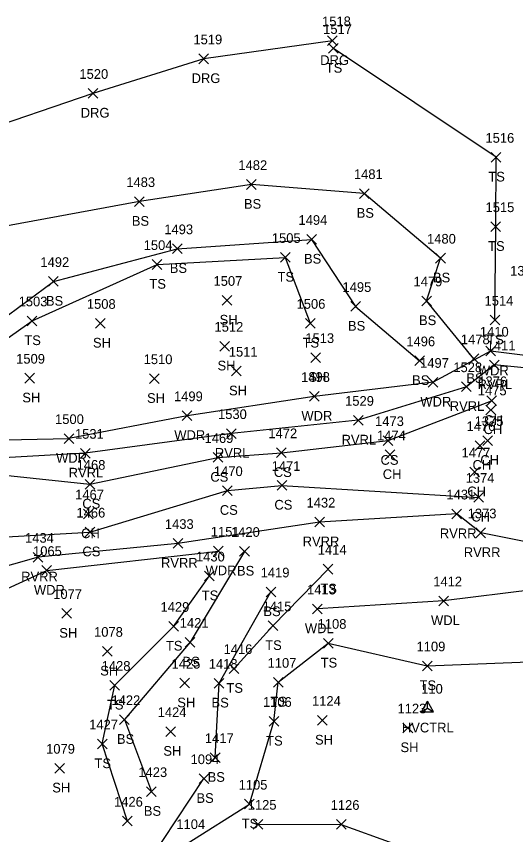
# Model space of a CAD drawing. Extents: x 1621633 to 1624015, y 417863 to 420979.
# Drawn here: x 1622010.4 to 1622113.6, y 418184 to 418353 of the extents above; entities that cross this region are included whole.
import ezdxf

# ---------------------------------------------------------------- set-up
doc = ezdxf.new("R2010")
doc.units = 0
for name, color, linetype in [('C_A', 7, 'Continuous'), ('C_I', 7, 'Continuous'), ('CPSM', 7, 'Continuous'), ('L_A', 7, 'Continuous'), ('L_I', 7, 'Continuous'), ('L_TIC', 7, 'Continuous'), ('LAWA', 7, 'Continuous'), ('LAWE', 7, 'Continuous'), ('LELB', 7, 'Continuous'), ('R_A', 7, 'Continuous'), ('R_I', 7, 'Continuous'), ('R_TIC', 7, 'Continuous'), ('RDG', 7, 'Continuous')]:
    doc.layers.add(name, color=color, linetype=linetype)

msp = doc.modelspace()

# ---------------------------------------------------------------- linework, layer by layer
at = {"layer": 'CPSM'}
for p, q in [((1622094.16, 418209.42), (1622095.41, 418211.59)), ((1622094.16, 418209.42), (1622095.41, 418210.14)), ((1622096.66, 418209.42), (1622095.41, 418211.59)), ((1622095.41, 418210.14), (1622095.41, 418211.59)), ((1622095.41, 418210.14), (1622095.41, 418210.14)), ((1622095.41, 418210.14), (1622096.66, 418209.42)), ((1622094.16, 418209.42), (1622096.66, 418209.42))]:
    msp.add_line(p, q, dxfattribs=at)
at = {"layer": 'L_TIC'}
for points in [[(1622074.96, 418345.37), (1622076.96, 418347.37)], [(1622076.96, 418345.37), (1622074.96, 418347.37)], [(1622108.55, 418322.9), (1622110.55, 418324.9)], [(1622110.55, 418322.9), (1622108.55, 418324.9)], [(1622058.02, 418317.28), (1622060.02, 418319.28)], [(1622060.02, 418317.28), (1622058.02, 418319.28)], [(1622081.32, 418315.41), (1622083.32, 418317.41)], [(1622083.32, 418315.41), (1622081.32, 418317.41)], [(1622034.86, 418313.76), (1622036.86, 418315.76)], [(1622036.86, 418313.76), (1622034.86, 418315.76)], [(1622108.51, 418308.58), (1622110.51, 418310.58)], [(1622110.51, 418308.58), (1622108.51, 418310.58)], [(1622070.43, 418305.95), (1622072.43, 418307.95)], [(1622072.43, 418305.95), (1622070.43, 418307.95)], [(1622042.7, 418304.02), (1622044.7, 418306.02)], [(1622044.7, 418304.02), (1622042.7, 418306.02)], [(1622065, 418302.22), (1622067, 418304.22)], [(1622067, 418302.22), (1622065, 418304.22)], [(1622097.08, 418302.07), (1622099.08, 418304.07)], [(1622099.08, 418302.07), (1622097.08, 418304.07)], [(1622038.52, 418300.76), (1622040.52, 418302.76)], [(1622040.52, 418300.76), (1622038.52, 418302.76)], [(1622017.11, 418297.26), (1622019.11, 418299.26)], [(1622019.11, 418297.26), (1622017.11, 418299.26)], [(1622052.95, 418293.36), (1622054.95, 418295.36)], [(1622054.95, 418293.36), (1622052.95, 418295.36)], [(1622094.2, 418293.25), (1622096.2, 418295.25)], [(1622096.2, 418293.25), (1622094.2, 418295.25)], [(1622079.52, 418292.1), (1622081.52, 418294.1)], [(1622081.52, 418292.1), (1622079.52, 418294.1)], [(1622012.68, 418289.12), (1622014.68, 418291.12)], [(1622014.68, 418289.12), (1622012.68, 418291.12)], [(1622108.31, 418289.28), (1622110.31, 418291.28)], [(1622110.31, 418289.28), (1622108.31, 418291.28)], [(1622026.78, 418288.61), (1622028.78, 418290.61)], [(1622028.78, 418288.61), (1622026.78, 418290.61)], [(1622070.17, 418288.62), (1622072.17, 418290.62)], [(1622072.17, 418288.62), (1622070.17, 418290.62)], [(1622052.51, 418283.89), (1622054.51, 418285.89)], [(1622054.51, 418283.89), (1622052.51, 418285.89)], [(1622107.44, 418282.87), (1622109.44, 418284.87)], [(1622109.44, 418282.87), (1622107.44, 418284.87)], [(1622071.27, 418281.55), (1622073.27, 418283.55)], [(1622073.27, 418281.55), (1622071.27, 418283.55)], [(1622092.77, 418280.88), (1622094.77, 418282.88)], [(1622094.77, 418280.88), (1622092.77, 418282.88)], [(1622103.98, 418281.3), (1622105.98, 418283.3)], [(1622105.98, 418281.3), (1622103.98, 418283.3)], [(1622108.18, 418280.03), (1622110.18, 418282.03)], [(1622110.18, 418280.03), (1622108.18, 418282.03)], [(1622012.18, 418277.29), (1622014.18, 418279.29)], [(1622014.18, 418277.29), (1622012.18, 418279.29)], [(1622054.9, 418278.74), (1622056.9, 418280.74)], [(1622056.9, 418278.74), (1622054.9, 418280.74)], [(1622037.95, 418277.19), (1622039.95, 418279.19)], [(1622039.95, 418277.19), (1622037.95, 418279.19)], [(1622095.55, 418276.43), (1622097.55, 418278.43)], [(1622097.55, 418276.43), (1622095.55, 418278.43)], [(1622102.42, 418275.53), (1622104.42, 418277.53)], [(1622104.42, 418275.53), (1622102.42, 418277.53)], [(1622070.98, 418273.52), (1622072.98, 418275.52)], [(1622072.98, 418273.52), (1622070.98, 418275.52)], [(1622107.64, 418272.64), (1622109.64, 418274.64)], [(1622109.64, 418272.64), (1622107.64, 418274.64)], [(1622107.48, 418270.74), (1622109.48, 418272.74)], [(1622109.48, 418270.74), (1622107.48, 418272.74)], [(1622044.71, 418269.54), (1622046.71, 418271.54)], [(1622046.71, 418269.54), (1622044.71, 418271.54)], [(1622080.07, 418268.59), (1622082.07, 418270.59)], [(1622082.07, 418268.59), (1622080.07, 418270.59)], [(1622053.89, 418265.85), (1622055.89, 418267.85)], [(1622055.89, 418265.85), (1622053.89, 418267.85)], [(1622020.3, 418264.82), (1622022.3, 418266.82)], [(1622022.3, 418264.82), (1622020.3, 418266.82)], [(1622086.25, 418264.4), (1622088.25, 418266.4)], [(1622088.25, 418264.4), (1622086.25, 418266.4)], [(1622106.83, 418264.41), (1622108.83, 418266.41)], [(1622108.83, 418264.41), (1622106.83, 418266.41)], [(1622105.21, 418263.38), (1622107.21, 418265.38)], [(1622107.21, 418263.38), (1622105.21, 418265.38)], [(1622023.68, 418261.78), (1622025.68, 418263.78)], [(1622025.68, 418261.78), (1622023.68, 418263.78)], [(1622051.08, 418260.91), (1622053.08, 418262.91)], [(1622053.08, 418260.91), (1622051.08, 418262.91)], [(1622064.2, 418261.89), (1622066.2, 418263.89)], [(1622066.2, 418261.89), (1622064.2, 418263.89)], [(1622086.66, 418261.47), (1622088.66, 418263.47)], [(1622088.66, 418261.47), (1622086.66, 418263.47)], [(1622104.12, 418257.91), (1622106.12, 418259.91)], [(1622106.12, 418257.91), (1622104.12, 418259.91)], [(1622024.63, 418255.38), (1622026.63, 418257.38)], [(1622026.63, 418255.38), (1622024.63, 418257.38)], [(1622053.04, 418254.07), (1622055.04, 418256.07)], [(1622055.04, 418254.07), (1622053.04, 418256.07)], [(1622064.32, 418255.15), (1622066.32, 418257.15)], [(1622066.32, 418255.15), (1622064.32, 418257.15)], [(1622104.96, 418252.68), (1622106.96, 418254.68)], [(1622106.96, 418252.68), (1622104.96, 418254.68)], [(1622024.33, 418249.25), (1622026.33, 418251.25)], [(1622026.33, 418249.25), (1622024.33, 418251.25)], [(1622100.43, 418249.25), (1622102.43, 418251.25)], [(1622102.43, 418249.25), (1622100.43, 418251.25)], [(1622072.09, 418247.58), (1622074.09, 418249.58)], [(1622074.09, 418247.58), (1622072.09, 418249.58)], [(1622024.65, 418245.51), (1622026.65, 418247.51)], [(1622026.65, 418245.51), (1622024.65, 418247.51)], [(1622105.38, 418245.35), (1622107.38, 418247.35)], [(1622107.38, 418245.35), (1622105.38, 418247.35)], [(1622042.82, 418243.16), (1622044.82, 418245.16)], [(1622044.82, 418243.16), (1622042.82, 418245.16)], [(1622013.93, 418240.31), (1622015.93, 418242.31)], [(1622015.93, 418240.31), (1622013.93, 418242.31)], [(1622051.18, 418241.59), (1622053.18, 418243.59)], [(1622053.18, 418241.59), (1622051.18, 418243.59)], [(1622056.58, 418241.52), (1622058.58, 418243.52)], [(1622058.58, 418241.52), (1622056.58, 418243.52)], [(1622015.71, 418237.58), (1622017.71, 418239.58)], [(1622017.71, 418237.58), (1622015.71, 418239.58)], [(1622073.85, 418237.85), (1622075.85, 418239.85)], [(1622075.85, 418237.85), (1622073.85, 418239.85)], [(1622049.34, 418236.44), (1622051.34, 418238.44)], [(1622051.34, 418236.44), (1622049.34, 418238.44)], [(1622062.05, 418233.15), (1622064.05, 418235.15)], [(1622064.05, 418233.15), (1622062.05, 418235.15)], [(1622097.7, 418231.3), (1622099.7, 418233.3)], [(1622099.7, 418231.3), (1622097.7, 418233.3)], [(1622019.83, 418228.7), (1622021.83, 418230.7)], [(1622021.83, 418228.7), (1622019.83, 418230.7)], [(1622071.64, 418229.63), (1622073.64, 418231.63)], [(1622073.64, 418229.63), (1622071.64, 418231.63)], [(1622041.93, 418226.04), (1622043.93, 418228.04)], [(1622043.93, 418226.04), (1622041.93, 418228.04)], [(1622062.45, 418226.16), (1622064.45, 418228.16)], [(1622064.45, 418226.16), (1622062.45, 418228.16)], [(1622045.33, 418222.76), (1622047.33, 418224.76)], [(1622047.33, 418222.76), (1622045.33, 418224.76)], [(1622073.9, 418222.54), (1622075.9, 418224.54)], [(1622075.9, 418222.54), (1622073.9, 418224.54)], [(1622028.27, 418220.89), (1622030.27, 418222.89)], [(1622030.27, 418220.89), (1622028.27, 418222.89)], [(1622054.44, 418217.32), (1622056.44, 418219.32)], [(1622056.44, 418217.32), (1622054.44, 418219.32)], [(1622094.34, 418217.88), (1622096.34, 418219.88)], [(1622096.34, 418217.88), (1622094.34, 418219.88)], [(1622029.76, 418213.87), (1622031.76, 418215.87)], [(1622031.76, 418213.87), (1622029.76, 418215.87)], [(1622044.2, 418214.32), (1622046.2, 418216.32)], [(1622046.2, 418214.32), (1622044.2, 418216.32)], [(1622051.33, 418214.29), (1622053.33, 418216.29)], [(1622053.33, 418214.29), (1622051.33, 418216.29)], [(1622063.55, 418214.49), (1622065.55, 418216.49)], [(1622065.55, 418214.49), (1622063.55, 418216.49)], [(1622031.78, 418206.78), (1622033.78, 418208.78)], [(1622033.78, 418206.78), (1622031.78, 418208.78)], [(1622062.65, 418206.42), (1622064.65, 418208.42)], [(1622064.65, 418206.42), (1622062.65, 418208.42)], [(1622072.66, 418206.63), (1622074.66, 418208.63)], [(1622074.66, 418206.63), (1622072.66, 418208.63)], [(1622090.33, 418205.07), (1622092.33, 418207.07)], [(1622092.33, 418205.07), (1622090.33, 418207.07)], [(1622041.33, 418204.32), (1622043.33, 418206.32)], [(1622043.33, 418204.32), (1622041.33, 418206.32)], [(1622027.18, 418201.76), (1622029.18, 418203.76)], [(1622029.18, 418201.76), (1622027.18, 418203.76)], [(1622050.52, 418198.94), (1622052.52, 418200.94)], [(1622052.52, 418198.94), (1622050.52, 418200.94)], [(1622018.37, 418196.74), (1622020.37, 418198.74)], [(1622020.37, 418196.74), (1622018.37, 418198.74)], [(1622048.21, 418194.59), (1622050.21, 418196.59)], [(1622050.21, 418194.59), (1622048.21, 418196.59)], [(1622037.34, 418191.92), (1622039.34, 418193.92)], [(1622039.34, 418191.92), (1622037.34, 418193.92)], [(1622057.58, 418189.33), (1622059.58, 418191.33)], [(1622059.58, 418189.33), (1622057.58, 418191.33)], [(1622032.38, 418185.82), (1622034.38, 418187.82)], [(1622034.38, 418185.82), (1622032.38, 418187.82)], [(1622059.38, 418185.18), (1622061.38, 418187.18)], [(1622061.38, 418185.18), (1622059.38, 418187.18)], [(1622076.57, 418185.15), (1622078.57, 418187.15)], [(1622078.57, 418185.15), (1622076.57, 418187.15)]]:
    msp.add_lwpolyline(points, dxfattribs=at)
at = {"layer": 'LAWA'}
for points in [[(1622334.14, 418235.62), (1622304.57, 418226.13), (1622279.17, 418224.78), (1622252.77, 418236.61), (1622231.24, 418254.76), (1622207.28, 418260.97), (1622182.84, 418269.19), (1622160.31, 418273.27), (1622129.81, 418281.16), (1622108.44, 418283.87), (1622096.55, 418277.43), (1622071.98, 418274.52), (1622045.71, 418270.54), (1622021.3, 418265.82)], [(1622001.65, 418265.43), (1622021.3, 418265.82)], [(1622320.21, 418157.08), (1622282.22, 418156.15), (1622251.71, 418155.08), (1622223.6, 418155.09), (1622209.11, 418155.31), (1622180.88, 418152.89), (1622152.12, 418150.87), (1622117.37, 418144.74), (1622094.14, 418141.69), (1622062.96, 418134.28), (1622030.01, 418125.89), (1622002.09, 418113.22), (1622001.94, 418118.19), (1622004.41, 418142.61), (1621992.55, 418166.21), (1621982.92, 418190.96), (1621974.22, 418213.57), (1621987.21, 418225.09), (1622016.71, 418238.58), (1622052.18, 418242.59)], [(1622294.12, 418161.35), (1622295.35, 418165.31), (1622279.05, 418165.1), (1622262.62, 418162.03), (1622241.27, 418162.89), (1622220.84, 418170.43), (1622210.97, 418182.32), (1622187.59, 418203.03), (1622170.53, 418217.1), (1622143.74, 418224.16), (1622117.62, 418234.62), (1622098.7, 418232.3), (1622072.64, 418230.63)]]:
    msp.add_lwpolyline(points, dxfattribs=at)
at = {"layer": 'LAWE'}
for points in [[(1622333.17, 418232.98), (1622304.92, 418224.43), (1622278.58, 418222.6), (1622250.59, 418234.06), (1622231.09, 418250.9), (1622207.09, 418257.63), (1622185.14, 418265.61), (1622157.85, 418271.29), (1622128.42, 418279.11), (1622109.18, 418281.03), (1622103.42, 418276.53), (1622081.07, 418269.59), (1622054.89, 418266.85), (1622024.68, 418262.78), (1621999.35, 418261.34), (1621980.1, 418259.35), (1621959.54, 418247.53), (1621949.11, 418230.91), (1621945.67, 418206.62), (1621950.84, 418182.3), (1621958.69, 418157.04), (1621962.92, 418133.77), (1621970.23, 418110.89)], [(1622323.31, 418180.93), (1622300.82, 418170.32), (1622276.31, 418168.44), (1622241.72, 418167.29), (1622221.82, 418173.51), (1622205.88, 418194.82), (1622185.97, 418220.63), (1622162.23, 418235.42), (1622129.82, 418241.7), (1622106.38, 418246.35), (1622101.43, 418250.25), (1622073.09, 418248.58), (1622043.82, 418244.16), (1622014.93, 418241.31), (1621989.87, 418234.25), (1621972.68, 418220.99), (1621964.49, 418204.33), (1621969.88, 418176.14), (1621978.91, 418154.62), (1621984.37, 418139.62), (1621989.94, 418122.86), (1621991.15, 418115.14)]]:
    msp.add_lwpolyline(points, dxfattribs=at)
at = {"layer": 'LELB'}
for points in [[(1622109.31, 418290.28), (1622109.51, 418309.58), (1622109.55, 418323.9), (1622075.96, 418346.37)], [(1622104.98, 418282.3), (1622095.2, 418294.25), (1622098.08, 418303.07), (1622082.32, 418316.41), (1622059.02, 418318.28), (1622035.86, 418314.76), (1622004.08, 418308.92), (1621989.1, 418291.93), (1621969.69, 418273.7), (1621958.77, 418259.65)], [(1621997.84, 418270.12), (1621990.09, 418277.31), (1621999.43, 418284.47), (1622018.11, 418298.26), (1622043.7, 418305.02), (1622071.43, 418306.95), (1622080.52, 418293.1), (1622093.77, 418281.88)], [(1621994.58, 418276.65), (1622013.68, 418290.12), (1622039.52, 418301.76), (1622066, 418303.22), (1622071.17, 418289.62)], [(1622087.25, 418265.4), (1622108.64, 418273.64)], [(1621966.69, 418246.42), (1621982.62, 418255.18), (1622002.13, 418258.88), (1622025.63, 418256.38), (1622052.08, 418261.91), (1622065.2, 418262.89), (1622087.25, 418265.4)], [(1621986.07, 418114.57), (1621980.01, 418135.51), (1621971.8, 418158.97), (1621964.78, 418178.35), (1621962.01, 418198.43), (1621960.3, 418210.78), (1621971.3, 418225.2), (1621983.84, 418236.14), (1622007.18, 418245.45), (1622025.65, 418246.51), (1622054.04, 418255.07), (1622065.32, 418256.15)], [(1622065.32, 418256.15), (1622105.96, 418253.68)], [(1622057.58, 418242.52), (1622046.33, 418223.76), (1622032.78, 418207.78), (1622038.34, 418192.92)], [(1622074.85, 418238.85), (1622063.45, 418227.16), (1622055.44, 418218.32)], [(1622033.38, 418186.82), (1622028.18, 418202.76), (1622030.76, 418214.87), (1622042.93, 418227.04), (1622050.34, 418237.44)], [(1622051.52, 418199.94), (1622052.33, 418215.29), (1622063.05, 418234.15)], [(1622012.96, 418144.68), (1622025.55, 418152.7), (1622030.18, 418148.41), (1622040.54, 418132.85), (1622043.38, 418133.51), (1622037.79, 418144.79), (1622034.62, 418151.12), (1622038.47, 418156.73), (1622040.15, 418173.27), (1622045.7, 418182.18), (1622058.58, 418190.33), (1622063.65, 418207.42), (1622064.55, 418215.49), (1622074.9, 418223.54), (1622095.34, 418218.88), (1622118.02, 418219.75), (1622146.4, 418210.35), (1622169.6, 418199.38), (1622194.43, 418184.07), (1622206.1, 418163.37)], [(1622008.25, 418147.12), (1622025.93, 418155.66), (1622030.02, 418153.88), (1622035.92, 418141.6), (1622039.51, 418135.23), (1622041.64, 418135.29), (1622035.33, 418145.89), (1622033.36, 418153.75), (1622037.76, 418161.1), (1622037.88, 418178.56), (1622049.21, 418195.59)], [(1622060.38, 418186.18), (1622077.57, 418186.15), (1622098.9, 418178.4), (1622113.36, 418166.93), (1622113.39, 418154.92)]]:
    msp.add_lwpolyline(points, dxfattribs=at)
at = {"layer": 'R_TIC'}
for points in [[(1622074.73, 418346.97), (1622076.73, 418348.97)], [(1622076.73, 418346.97), (1622074.73, 418348.97)], [(1622048.16, 418343.23), (1622050.16, 418345.23)], [(1622050.16, 418343.23), (1622048.16, 418345.23)], [(1622025.25, 418336.1), (1622027.25, 418338.1)], [(1622027.25, 418336.1), (1622025.25, 418338.1)]]:
    msp.add_lwpolyline(points, dxfattribs=at)
at = {"layer": 'RDG'}
msp.add_lwpolyline([(1622075.73, 418347.97), (1622049.16, 418344.23), (1622026.25, 418337.1), (1622001.6, 418328.7), (1621987.27, 418324.78), (1621966.53, 418312.68)], dxfattribs=at)

# ---------------------------------------------------------------- texts
at = {"layer": 'C_A'}
msp.add_text('HVCTRL', height=2, dxfattribs=at).set_placement((1622090.1, 418205.14))
at = {"layer": 'C_I'}
msp.add_text('110', height=2, dxfattribs=at).set_placement((1622094.09, 418213.14))
at = {"layer": 'L_A'}
for s, p in [('TS', (1622074.37, 418341.37)), ('TS', (1622107.96, 418318.9)), ('BS', (1622057.46, 418313.28)), ('BS', (1622080.76, 418311.41)), ('BS', (1622034.3, 418309.76)), ('TS', (1622107.92, 418304.58)), ('BS', (1622069.87, 418301.95)), ('BS', (1622042.14, 418300.02)), ('TS', (1622064.41, 418298.22)), ('BS', (1622096.52, 418298.07)), ('TS', (1622037.93, 418296.76)), ('BS', (1622016.55, 418293.26)), ('SH', (1622052.44, 418289.36)), ('BS', (1622093.64, 418289.25)), ('BS', (1622078.96, 418288.1)), ('TS', (1622012.09, 418285.12)), ('SH', (1622026.27, 418284.61)), ('TS', (1622069.58, 418284.62)), ('TS', (1622107.72, 418285.28)), ('SH', (1622052, 418279.89)), ('SH', (1622070.76, 418277.55)), ('BS', (1622103.42, 418277.3)), ('WDR', (1622105.8, 418278.87)), ('BS', (1622092.21, 418276.88)), ('RVRL', (1622105.74, 418276.03)), ('SH', (1622054.39, 418274.74)), ('SH', (1622011.67, 418273.29)), ('SH', (1622037.44, 418273.19)), ('WDR', (1622093.92, 418272.43)), ('RVRL', (1622099.99, 418271.53)), ('WDR', (1622069.34, 418269.52)), ('CH', (1622107.12, 418268.64)), ('WDR', (1622043.07, 418265.54)), ('CH', (1622106.97, 418266.74)), ('RVRL', (1622077.64, 418264.59)), ('WDR', (1622018.66, 418260.82)), ('RVRL', (1622051.46, 418261.85)), ('CS', (1622085.69, 418260.4)), ('CH', (1622106.32, 418260.41)), ('CH', (1622104.7, 418259.38)), ('RVRL', (1622021.25, 418257.78)), ('CS', (1622050.52, 418256.91)), ('CS', (1622063.64, 418257.89)), ('CH', (1622086.15, 418257.47)), ('CH', (1622103.61, 418253.91)), ('CS', (1622024.07, 418251.38)), ('CS', (1622063.76, 418251.15)), ('CS', (1622052.48, 418250.07)), ('CH', (1622104.45, 418248.68)), ('CH', (1622023.82, 418245.25)), ('RVRR', (1622097.94, 418245.25)), ('RVRR', (1622069.6, 418243.58)), ('CS', (1622024.09, 418241.51)), ('RVRR', (1622102.89, 418241.35)), ('RVRR', (1622040.33, 418239.16)), ('WDR', (1622049.54, 418237.59)), ('BS', (1622056.02, 418237.52)), ('RVRR', (1622011.44, 418236.31)), ('WDR', (1622014.07, 418233.58)), ('TS', (1622073.26, 418233.85)), ('TS', (1622048.75, 418232.44)), ('BS', (1622061.49, 418229.15)), ('WDL', (1622096.12, 418227.3)), ('WDL', (1622070.06, 418225.63)), ('SH', (1622019.31, 418224.7)), ('TS', (1622041.34, 418222.04)), ('TS', (1622061.86, 418222.16)), ('BS', (1622044.77, 418218.76)), ('TS', (1622073.31, 418218.54)), ('SH', (1622027.76, 418216.89)), ('TS', (1622053.85, 418213.32)), ('TS', (1622093.75, 418213.88)), ('TS', (1622029.17, 418209.87)), ('SH', (1622043.69, 418210.32)), ('BS', (1622050.77, 418210.29)), ('TS', (1622062.96, 418210.49)), ('BS', (1622031.22, 418202.78)), ('TS', (1622062.06, 418202.42)), ('SH', (1622072.15, 418202.63)), ('SH', (1622040.82, 418200.32)), ('SH', (1622089.81, 418201.07)), ('TS', (1622026.59, 418197.76)), ('BS', (1622049.96, 418194.94)), ('SH', (1622017.86, 418192.74)), ('BS', (1622047.65, 418190.59)), ('BS', (1622036.78, 418187.92)), ('TS', (1622056.99, 418185.33))]:
    msp.add_text(s, height=2, dxfattribs=at).set_placement(p)
at = {"layer": 'L_I'}
for s, p in [('1517', (1622073.83, 418349.37)), ('1516', (1622107.37, 418326.9)), ('1482', (1622056.32, 418321.28)), ('1483', (1622033.16, 418317.76)), ('1481', (1622080.19, 418319.41)), ('1515', (1622107.38, 418312.58)), ('1494', (1622068.74, 418309.95)), ('1493', (1622041.01, 418308.02)), ('1505', (1622063.23, 418306.22)), ('1480', (1622095.3, 418306.07)), ('1504', (1622036.75, 418304.76)), ('1492', (1622015.41, 418301.26)), ('1377', (1622112.47, 418299.46)), ('1507', (1622051.18, 418297.36)), ('1495', (1622077.83, 418296.1)), ('1479', (1622092.5, 418297.25)), ('1503', (1622010.91, 418293.12)), ('1508', (1622025.01, 418292.61)), ('1506', (1622068.34, 418292.62)), ('1514', (1622107.18, 418293.28)), ('1512', (1622051.38, 418287.89)), ('1410', (1622106.22, 418286.87)), ('1513', (1622070.15, 418285.55)), ('1496', (1622091.02, 418284.88)), ('1478', (1622102.29, 418285.3)), ('1411', (1622107.62, 418284.03)), ('1511', (1622054.34, 418282.74)), ('1509', (1622010.4, 418281.29)), ('1510', (1622036.74, 418281.19)), ('1497', (1622093.86, 418280.43)), ('1528', (1622100.73, 418279.53)), ('1498', (1622069.28, 418277.52)), ('1376', (1622105.89, 418276.64)), ('1475', (1622105.79, 418274.74)), ('1499', (1622043.01, 418273.54)), ('1529', (1622078.37, 418272.59)), ('1500', (1622018.44, 418268.82)), ('1530', (1622052.11, 418269.85)), ('1473', (1622084.56, 418268.4)), ('1476', (1622103.46, 418267.38)), ('1375', (1622105.14, 418268.41)), ('1531', (1622022.55, 418265.78)), ('1472', (1622062.51, 418265.89)), ('1474', (1622084.97, 418265.47)), ('1469', (1622049.33, 418264.91)), ('1477', (1622102.43, 418261.91)), ('1468', (1622022.89, 418259.38)), ('1471', (1622063.19, 418259.15)), ('1470', (1622051.26, 418258.07)), ('1374', (1622103.27, 418256.68)), ('1467', (1622022.59, 418253.25)), ('1431', (1622099.3, 418253.25)), ('1432', (1622070.4, 418251.58)), ('1466', (1622022.86, 418249.51)), ('1373', (1622103.69, 418249.35)), ('1433', (1622041.13, 418247.16)), ('1151', (1622050.62, 418245.59)), ('1420', (1622054.8, 418245.52)), ('1434', (1622012.24, 418244.31)), ('1414', (1622072.72, 418241.85)), ('1065', (1622013.89, 418241.58)), ('1430', (1622047.56, 418240.44)), ('1419', (1622060.92, 418237.15)), ('1412', (1622096.58, 418235.3)), ('1413', (1622070.51, 418233.63)), ('1077', (1622018.05, 418232.7)), ('1429', (1622040.23, 418230.04)), ('1415', (1622061.33, 418230.16)), ('1421', (1622044.2, 418226.76)), ('1108', (1622072.69, 418226.54)), ('1078', (1622026.5, 418224.89)), ('1109', (1622093.13, 418221.88)), ('1416', (1622053.26, 418221.32)), ('1425', (1622042.51, 418218.32)), ('1418', (1622050.2, 418218.29)), ('1107', (1622062.35, 418218.49)), ('1428', (1622028.07, 418217.87)), ('1422', (1622030.09, 418210.78)), ('1106', (1622061.39, 418210.42)), ('1124', (1622071.53, 418210.63)), ('1424', (1622039.64, 418208.32)), ('1123', (1622089.2, 418209.07)), ('1427', (1622025.49, 418205.76)), ('1417', (1622049.4, 418202.94)), ('1079', (1622016.59, 418200.74)), ('1094', (1622046.44, 418198.59)), ('1423', (1622035.65, 418195.92)), ('1105', (1622056.37, 418193.33)), ('1426', (1622030.63, 418189.82)), ('1125', (1622058.25, 418189.18)), ('1126', (1622075.39, 418189.15)), ('1104', (1622043.5, 418185.18))]:
    msp.add_text(s, height=2, dxfattribs=at).set_placement(p)
at = {"layer": 'R_A'}
for p in [(1622073.22, 418342.97), (1622046.65, 418339.23), (1622023.74, 418332.1)]:
    msp.add_text('DRG', height=2, dxfattribs=at).set_placement(p)
at = {"layer": 'R_I'}
for s, p in [('1518', (1622073.61, 418350.97)), ('1519', (1622047.03, 418347.23)), ('1520', (1622023.47, 418340.1))]:
    msp.add_text(s, height=2, dxfattribs=at).set_placement(p)

doc.saveas('drawing.dxf')
